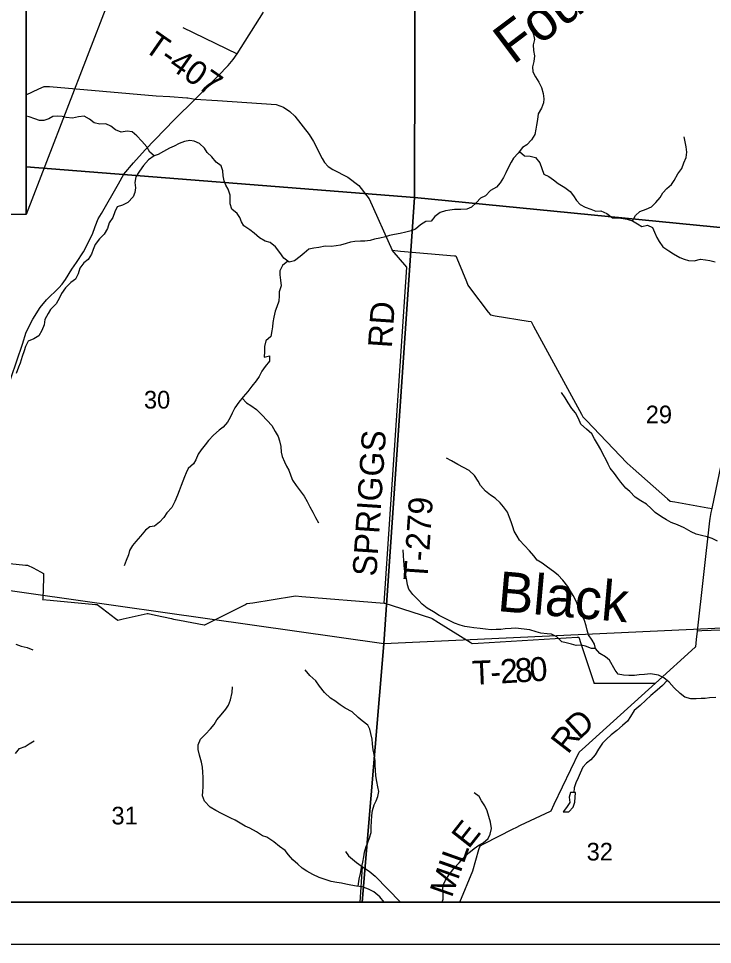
# Model space of a CAD drawing. Extents: x 0 to 34, y 0 to 22.
# Drawn here: x 26.174 to 27.818, y 14 to 16.193 of the extents above; entities that cross this region are included whole.
import ezdxf

# ---------------------------------------------------------------- set-up
doc = ezdxf.new("R2010")
doc.units = 0
for name, color, linetype in [('GM_X_Corporation', 7, 'Continuous'), ('GM_X_County_Road', 7, 'Continuous'), ('GM_X_County_Road_Text', 7, 'Continuous'), ('GM_X_Minor_Lake', 7, 'Continuous'), ('GM_X_Minor_River', 7, 'Continuous'), ('GM_X_Minor_River_Text', 7, 'Continuous'), ('GM_X_Section_Text', 7, 'Continuous'), ('GM_X_State_Route', 7, 'Continuous'), ('GM_X_Township_Road', 7, 'Continuous'), ('GM_X_Township_Road_Text', 7, 'Continuous'), ('SH_Data', 7, 'Continuous')]:
    doc.layers.add(name, color=color, linetype=linetype)

msp = doc.modelspace()

# ---------------------------------------------------------------- linework, layer by layer
at = {"layer": 'GM_X_Corporation'}
for points in [[(25.8273, 14.1), (30.3167, 14.1), (30.3167, 19.5906)], [(26.0314, 16.5691), (26.06, 16.9257), (27.1145, 16.8163), (27.112, 15.7689), (26.1924, 15.8415)], [(26.1924, 15.8415), (27.112, 15.7689), (27.0394, 14.7121), (25.8914, 14.8743), (25.8953, 14.9265), (25.9642, 15.7291)]]:
    msp.add_lwpolyline(points, dxfattribs=at)
for points in [[(27.1145, 16.8163), (28.199, 16.7653), (28.1104, 15.671), (27.112, 15.7689)], [(28.1104, 15.671), (28.0453, 14.7589), (27.0394, 14.7121), (27.112, 15.7689)], [(25.8293, 14.1), (26.9884, 14.1), (27.0394, 14.7121), (25.8914, 14.8743)], [(26.9884, 14.1), (27.9368, 14.1), (28.0453, 14.7589), (27.0394, 14.7121)]]:
    msp.add_lwpolyline(points, close=True, dxfattribs=at)
at = {"layer": 'GM_X_County_Road'}
for points in [[(27.2199, 14.1), (27.2503, 14.1742), (27.2643, 14.2249), (27.2676, 14.2334), (27.2768, 14.2381), (27.3461, 14.2739), (27.353, 14.2774), (27.3636, 14.2824), (27.4341, 14.3158), (27.4357, 14.3165), (27.4434, 14.3325), (27.5026, 14.4554), (27.5169, 14.4686), (27.6831, 14.6189), (27.777, 14.7039), (27.7783, 14.705), (27.7802, 14.7227), (27.7824, 14.7421), (27.8119, 15.0035), (27.8124, 15.0085), (27.8153, 15.0227), (27.8173, 15.0322), (27.9461, 15.6525)], [(28.0576, 14.1), (28.0667, 14.1974), (28.0669, 14.1999), (28.05, 14.2031), (27.953, 14.2215), (27.9558, 14.2408), (28.0358, 14.7517), (27.7925, 14.7425), (27.7824, 14.7421)]]:
    msp.add_lwpolyline(points, dxfattribs=at)
at = {"layer": 'GM_X_Minor_Lake'}
for points in [[(27.4935, 14.3597), (27.4818, 14.3598), (27.4787, 14.3492), (27.4798, 14.3363), (27.4726, 14.3242), (27.4642, 14.3144), (27.4722, 14.3141)], [(27.4722, 14.3141), (27.4775, 14.3139), (27.4877, 14.3253), (27.4923, 14.337), (27.4935, 14.3597)]]:
    msp.add_lwpolyline(points, dxfattribs=at)
at = {"layer": 'GM_X_Minor_River'}
for points in [[(27.3868, 16.1947), (27.3879, 16.1777), (27.389, 16.1678), (27.3939, 16.1553), (27.3961, 16.1431), (27.3934, 16.1306), (27.3937, 16.117), (27.3967, 16.1045), (27.3951, 16.0912), (27.3917, 16.0787), (27.3924, 16.0669), (27.3992, 16.0548), (27.4071, 16.0426), (27.4131, 16.0297), (27.4168, 16.0153), (27.4186, 16.0028), (27.4175, 15.9933), (27.4133, 15.9804), (27.4049, 15.9676), (27.4037, 15.9536), (27.401, 15.9407), (27.3998, 15.9312), (27.3975, 15.9187), (27.3891, 15.9055), (27.3781, 15.8941), (27.3683, 15.8877), (27.358, 15.8741), (27.347, 15.8624), (27.3409, 15.8526), (27.3337, 15.8394), (27.3287, 15.8272), (27.323, 15.8167), (27.3154, 15.8038), (27.3063, 15.7936), (27.2919, 15.7861), (27.2805, 15.7732), (27.2687, 15.7676), (27.2592, 15.7574)], [(26.4951, 15.8676), (26.4853, 15.8763), (26.4778, 15.8889), (26.4661, 15.9026), (26.454, 15.9151), (26.4431, 15.9243), (26.4314, 15.9262), (26.4174, 15.924), (26.4041, 15.9293), (26.3928, 15.9381), (26.3811, 15.9438), (26.3671, 15.9431), (26.3531, 15.9458), (26.3426, 15.9546), (26.3293, 15.9615), (26.3161, 15.9604), (26.3017, 15.9574), (26.2873, 15.9586), (26.2775, 15.9613), (26.2654, 15.9621), (26.2556, 15.961), (26.2461, 15.9557), (26.234, 15.9512), (26.2234, 15.9512), (26.2124, 15.9558), (26.1996, 15.9604), (26.1924, 15.962)], [(27.2592, 15.7574), (27.2471, 15.7461), (27.2361, 15.7412), (27.2221, 15.7408), (27.2073, 15.7409), (27.1956, 15.7394), (27.1854, 15.7372), (27.1729, 15.7335), (27.1604, 15.724), (27.152, 15.7134), (27.1391, 15.7124), (27.1262, 15.7044), (27.1145, 15.6939), (27.1046, 15.6901), (27.0914, 15.6871), (27.0785, 15.6838), (27.0649, 15.6812), (27.0531, 15.6789), (27.0433, 15.676), (27.0304, 15.673), (27.0175, 15.6704), (27.0069, 15.6674), (26.9944, 15.6659), (26.9839, 15.6659), (26.971, 15.6652), (26.9608, 15.6634), (26.9505, 15.6604), (26.9365, 15.6563), (26.9267, 15.6544), (26.9146, 15.6533), (26.9002, 15.6538), (26.8854, 15.6504), (26.8737, 15.6493), (26.8616, 15.6471), (26.8506, 15.6373), (26.8411, 15.629), (26.8282, 15.6195), (26.8149, 15.6162), (26.8029, 15.6257), (26.7935, 15.6386), (26.7825, 15.6523), (26.7705, 15.6626), (26.758, 15.6657), (26.7452, 15.6733), (26.7324, 15.6847), (26.7222, 15.6927), (26.7082, 15.7023), (26.7026, 15.7118), (26.6981, 15.722), (26.692, 15.7315), (26.6792, 15.7414), (26.6751, 15.7543), (26.6755, 15.7642), (26.6752, 15.7748), (26.6707, 15.7888), (26.6651, 15.7987), (26.6609, 15.8089), (26.6591, 15.8207), (26.6584, 15.8321), (26.6539, 15.8442), (26.6426, 15.853), (26.632, 15.8652), (26.6207, 15.8758), (26.6143, 15.8857), (26.6026, 15.8967), (26.5902, 15.9025), (26.5796, 15.904), (26.5675, 15.9018), (26.555, 15.8973), (26.5425, 15.8909), (26.5315, 15.886), (26.5178, 15.8777), (26.5049, 15.871), (26.4951, 15.8676), (26.4822, 15.8585), (26.4704, 15.8446), (26.4609, 15.8313), (26.4521, 15.8181), (26.4498, 15.8044), (26.4513, 15.7919), (26.4494, 15.7806), (26.4459, 15.7707), (26.4334, 15.7571), (26.4201, 15.7507), (26.408, 15.747), (26.4019, 15.7353), (26.3977, 15.7216), (26.3889, 15.7092), (26.3847, 15.6959), (26.3771, 15.6823), (26.3661, 15.6713), (26.3555, 15.6581), (26.3509, 15.6456), (26.3471, 15.635), (26.3391, 15.6222), (26.3292, 15.6142), (26.3193, 15.6014), (26.3155, 15.5881), (26.309, 15.576), (26.2984, 15.5681), (26.2851, 15.5553)], [(27.6286, 15.714), (27.6355, 15.7267), (27.6458, 15.7358), (27.6613, 15.7418), (27.6734, 15.7467), (27.6841, 15.7576), (27.6939, 15.7694), (27.7008, 15.7803), (27.7103, 15.7901), (27.7213, 15.7996), (27.727, 15.8094), (27.7361, 15.8253), (27.7453, 15.8382), (27.7502, 15.8514), (27.7556, 15.8639), (27.7575, 15.8764), (27.7557, 15.8889), (27.7534, 15.9007), (27.7508, 15.9128)], [(27.3608, 15.8779), (27.3724, 15.868), (27.3864, 15.8672), (27.3988, 15.8641), (27.4094, 15.8512), (27.4142, 15.8379), (27.4187, 15.8246), (27.4304, 15.8185), (27.4414, 15.8109), (27.4523, 15.8021), (27.4686, 15.793), (27.481, 15.7831), (27.4885, 15.7732), (27.4961, 15.7622), (27.5043, 15.7527), (27.5168, 15.7462), (27.5296, 15.7412), (27.5421, 15.7366), (27.5538, 15.7373), (27.5682, 15.7312), (27.581, 15.7213), (27.595, 15.7208), (27.6064, 15.7193), (27.6162, 15.7181), (27.629, 15.7139), (27.6407, 15.7066), (27.6506, 15.7002), (27.6642, 15.7035), (27.6759, 15.6978), (27.6811, 15.6868), (27.6864, 15.6746), (27.692, 15.6647), (27.7003, 15.6526), (27.7143, 15.6427), (27.726, 15.6354), (27.7411, 15.627), (27.7509, 15.6228), (27.7611, 15.6201), (27.7751, 15.6193), (27.7895, 15.6227), (27.8012, 15.6215), (27.8122, 15.6196), (27.8246, 15.6169)], [(26.812, 15.6185), (26.7998, 15.6079), (26.7929, 15.5954), (26.7929, 15.5859), (26.7951, 15.573), (26.7962, 15.5601), (26.7912, 15.5461), (26.7916, 15.5363), (26.7908, 15.5238), (26.7858, 15.5102), (26.7824, 15.5003), (26.7793, 15.4859), (26.7762, 15.473), (26.7754, 15.4628), (26.7742, 15.453), (26.7719, 15.4401), (26.7602, 15.4299), (26.7567, 15.4166), (26.7567, 15.4045), (26.7559, 15.3912), (26.7687, 15.3938), (26.7687, 15.3813), (26.7584, 15.3685), (26.7508, 15.3579), (26.744, 15.345), (26.7371, 15.3352), (26.7269, 15.322), (26.7177, 15.3095), (26.7063, 15.2974), (26.6957, 15.2846), (26.6869, 15.271), (26.6801, 15.2585), (26.6755, 15.2479), (26.6694, 15.2373), (26.6592, 15.2252), (26.6493, 15.2177), (26.636, 15.2063), (26.6239, 15.1935), (26.6163, 15.1837), (26.6068, 15.1712), (26.5999, 15.161), (26.5938, 15.1481), (26.5885, 15.1383), (26.5756, 15.127), (26.571, 15.1171), (26.5672, 15.1073), (26.563, 15.0975), (26.5592, 15.0869), (26.5549, 15.0744), (26.5504, 15.0645), (26.5443, 15.049), (26.537, 15.035), (26.5252, 15.0226), (26.518, 15.0116), (26.5078, 15.0003), (26.496, 14.9904), (26.485, 14.9893), (26.4748, 14.9814), (26.4634, 14.9674), (26.452, 14.9546), (26.444, 14.9448), (26.4371, 14.9327), (26.4348, 14.9228), (26.4291, 14.9092), (26.4242, 14.8971)], [(26.2851, 15.5553), (26.2756, 15.542), (26.271, 15.5314), (26.2634, 15.5171), (26.2501, 15.5042), (26.244, 15.4944), (26.2368, 15.4804), (26.2345, 15.4675), (26.2295, 15.4543), (26.2219, 15.4418), (26.2101, 15.4343), (26.1972, 15.4286), (26.1904, 15.4165), (26.1873, 15.4063), (26.1827, 15.3923), (26.1778, 15.3771), (26.1743, 15.3669), (26.1682, 15.3522)], [(26.7037, 15.2942), (26.7138, 15.283), (26.7244, 15.2765), (26.738, 15.267), (26.7501, 15.2544), (26.7632, 15.2411), (26.7738, 15.2289), (26.7821, 15.2153), (26.7892, 15.2031), (26.7926, 15.1932), (26.7952, 15.1796), (26.7966, 15.1659), (26.7985, 15.1557), (26.8045, 15.1432), (26.8086, 15.1329), (26.8143, 15.1234), (26.8195, 15.1101), (26.8233, 15.0999), (26.8319, 15.0873), (26.8511, 15.0615), (26.8579, 15.049), (26.8639, 15.0364), (26.871, 15.0235), (26.8778, 15.011), (26.8845, 14.9988)], [(27.8298, 14.9554), (27.8177, 14.9615), (27.8056, 14.9657), (27.792, 14.9688), (27.7791, 14.9719), (27.7678, 14.9772), (27.7512, 14.9868), (27.7353, 14.9937), (27.7202, 14.9994), (27.7089, 15.0055), (27.6972, 15.0131), (27.6825, 15.0234), (27.6727, 15.0326), (27.6614, 15.0425), (27.6485, 15.0505), (27.6349, 15.0596), (27.6225, 15.0725), (27.6127, 15.0809), (27.601, 15.0946), (27.5939, 15.1041), (27.586, 15.1155), (27.5754, 15.1281), (27.5709, 15.1379), (27.566, 15.1478), (27.5589, 15.1607), (27.5536, 15.1725), (27.5454, 15.1854), (27.5386, 15.1972), (27.5322, 15.2094), (27.5198, 15.2204), (27.5062, 15.2322), (27.501, 15.2455), (27.4938, 15.2588), (27.4852, 15.2694), (27.4761, 15.2831), (27.4694, 15.2949), (27.4607, 15.307)], [(27.7796, 14.5819), (27.7671, 14.5815), (27.7524, 14.5854), (27.7418, 14.5941), (27.7271, 14.6078), (27.7154, 14.6211), (27.703, 14.6314), (27.6901, 14.6379), (27.6712, 14.6406), (27.6572, 14.6396), (27.6447, 14.6385), (27.633, 14.637), (27.6201, 14.6374), (27.6073, 14.6375), (27.5944, 14.6402), (27.5873, 14.6497), (27.5741, 14.6736), (27.5643, 14.6812), (27.5511, 14.6889), (27.5413, 14.701), (27.5387, 14.7113), (27.5334, 14.7211), (27.524, 14.7333), (27.5214, 14.7447), (27.5192, 14.7549), (27.5147, 14.7671), (27.5087, 14.7804), (27.5034, 14.7902), (27.4993, 14.8032), (27.4948, 14.8134), (27.4884, 14.8267), (27.4817, 14.8366), (27.4756, 14.848), (27.4636, 14.8632), (27.4527, 14.875), (27.4414, 14.883), (27.427, 14.8936), (27.4149, 14.9032), (27.4029, 14.9104), (27.3946, 14.9207), (27.3844, 14.9325), (27.3611, 14.9576), (27.3554, 14.9671), (27.3486, 14.9792), (27.3453, 14.9891), (27.3412, 15.0009), (27.3374, 15.0115), (27.3325, 15.0236), (27.3228, 15.0362), (27.3148, 15.0457), (27.3035, 15.0567), (27.2922, 15.064), (27.2801, 15.0739), (27.2685, 15.0868), (27.2632, 15.0971), (27.2546, 15.1111), (27.2417, 15.1225), (27.2285, 15.1298), (27.2146, 15.1367), (27.2002, 15.1454), (27.1877, 15.1515)], [(27.5417, 14.7006), (27.5315, 14.7011), (27.5171, 14.7068), (27.5073, 14.7087), (27.4948, 14.708), (27.4838, 14.7111), (27.4718, 14.7146), (27.4615, 14.7169), (27.4495, 14.7283), (27.437, 14.7348), (27.4264, 14.7356), (27.4117, 14.7375), (27.4007, 14.7402), (27.3856, 14.7452), (27.3652, 14.7479), (27.3523, 14.7488), (27.341, 14.7484), (27.3266, 14.7473), (27.3168, 14.7462), (27.3054, 14.7459), (27.2941, 14.7452), (27.2804, 14.7464), (27.2676, 14.7487), (27.2528, 14.7499), (27.2423, 14.7518), (27.2317, 14.7534), (27.2207, 14.7565), (27.2067, 14.7611), (27.1803, 14.7744), (27.1705, 14.779), (27.1573, 14.7882), (27.1418, 14.7966), (27.1305, 14.8057), (27.1218, 14.8156), (27.1082, 14.8285), (27.0985, 14.8418), (27.0955, 14.8521), (27.094, 14.8619), (27.0918, 14.8748), (27.0888, 14.8885), (27.0877, 14.8991), (27.0866, 14.9086), (27.0863, 14.9211), (27.0852, 14.9344)], [(26.1677, 14.7112), (26.1806, 14.7066), (26.1949, 14.7035), (26.2082, 14.6978)], [(26.9785, 14.1379), (26.9813, 14.1548), (26.9844, 14.1684), (26.9867, 14.1817), (26.9894, 14.1953), (26.9921, 14.2078), (26.9936, 14.2184), (26.9978, 14.232), (27.0013, 14.2419), (27.0059, 14.2525), (27.0093, 14.2653), (27.0097, 14.2786), (27.0102, 14.2915), (27.011, 14.3051), (27.0125, 14.3172), (27.0164, 14.3305), (27.0213, 14.3403), (27.0251, 14.3502), (27.0278, 14.3623), (27.0252, 14.3733), (27.0226, 14.3862), (27.0208, 14.3991), (27.0201, 14.4139), (27.019, 14.4248), (27.019, 14.4347), (27.0164, 14.4499), (27.0142, 14.4609), (27.0127, 14.4749), (27.0116, 14.4859), (27.009, 14.4995), (27.0061, 14.5098), (27.0016, 14.5197), (26.9884, 14.5299), (26.9785, 14.5379), (26.9642, 14.5509), (26.948, 14.5597), (26.9363, 14.5677), (26.9231, 14.5768), (26.9129, 14.5837), (26.8986, 14.597), (26.8873, 14.6118), (26.8786, 14.6247), (26.8643, 14.6369), (26.8534, 14.6502)], [(26.6117, 14.373), (26.6114, 14.3828), (26.6118, 14.3957), (26.6107, 14.4082), (26.61, 14.4203), (26.6078, 14.4321), (26.6029, 14.448), (26.5996, 14.4617), (26.5996, 14.4727), (26.6053, 14.4863), (26.6167, 14.4984), (26.6289, 14.5109), (26.6373, 14.5211), (26.6441, 14.532), (26.654, 14.5441), (26.665, 14.557), (26.6718, 14.5668), (26.6764, 14.5793), (26.6799, 14.5967), (26.6811, 14.61)], [(27.7108, 14.625), (27.6999, 14.6136), (27.6873, 14.6027), (27.6722, 14.5899), (27.6604, 14.5785), (27.6464, 14.5657), (27.6327, 14.554), (27.6239, 14.54), (27.6171, 14.5291), (27.6046, 14.5185), (27.5913, 14.5068), (27.5784, 14.4962), (27.5674, 14.486), (27.5575, 14.4766), (27.5484, 14.4622), (27.5404, 14.4494), (27.5297, 14.4373), (27.5199, 14.4297), (27.5111, 14.4199), (27.5047, 14.4059), (27.4997, 14.395), (27.494, 14.3829), (27.4901, 14.3711), (27.4896, 14.3598)], [(27.8257, 14.5847), (27.811, 14.5844), (27.8008, 14.5829), (27.7909, 14.5826), (27.7796, 14.5819)], [(26.1672, 14.4524), (26.1767, 14.4644), (26.1895, 14.4686), (26.199, 14.4754), (26.2111, 14.4825)], [(27.0402, 14.1), (27.0299, 14.1125), (27.0156, 14.1243), (27.0031, 14.1308), (26.9884, 14.1366), (26.9744, 14.1385), (26.9612, 14.1405), (26.9495, 14.1428), (26.9393, 14.1451), (26.9283, 14.1466), (26.9147, 14.149), (26.9007, 14.1536), (26.886, 14.1589), (26.8716, 14.1654), (26.8569, 14.1738), (26.846, 14.1807), (26.8354, 14.1906), (26.8241, 14.2001), (26.8135, 14.2123), (26.8056, 14.2225), (26.7924, 14.2321), (26.7792, 14.2431), (26.7626, 14.2538), (26.7524, 14.2576), (26.7377, 14.2671), (26.7222, 14.2751), (26.7109, 14.2805), (26.6988, 14.2874), (26.6871, 14.2942), (26.6769, 14.2988), (26.6648, 14.3053), (26.6546, 14.3103), (26.6418, 14.3171), (26.6282, 14.3255), (26.615, 14.3392), (26.6101, 14.3521), (26.6109, 14.3624), (26.6117, 14.373)], [(27.1776, 14.1), (27.1797, 14.1074), (27.1801, 14.118), (27.179, 14.1301), (27.1802, 14.1408), (27.1859, 14.1525), (27.1954, 14.1665), (27.205, 14.1801), (27.2182, 14.1937), (27.2266, 14.2035), (27.2407, 14.2167), (27.2539, 14.2276), (27.2649, 14.2352), (27.2748, 14.2408), (27.2869, 14.251), (27.2915, 14.2612), (27.2942, 14.2749), (27.292, 14.2893), (27.2879, 14.3033), (27.2841, 14.3162), (27.2789, 14.328), (27.271, 14.3405), (27.2654, 14.3504), (27.2537, 14.3595)]]:
    msp.add_lwpolyline(points, dxfattribs=at)
at = {"layer": 'GM_X_State_Route'}
msp.add_lwpolyline([(26.1429, 15.303), (26.1832, 15.4214), (26.1922, 15.4498), (26.2078, 15.481), (26.2255, 15.5086), (26.2404, 15.5264), (26.2693, 15.5555), (26.2776, 15.5641), (26.2852, 15.5752), (26.3003, 15.5991), (26.3118, 15.6155), (26.3281, 15.6403), (26.3493, 15.6819), (26.3557, 15.7007), (26.3626, 15.7189), (26.3703, 15.7311), (26.4113, 15.8016), (26.4236, 15.8242), (26.4462, 15.8509), (26.4738, 15.8821), (26.5433, 15.954), (26.5927, 16.0024), (26.6473, 16.0575), (26.6709, 16.0819), (26.6827, 16.0959), (26.692, 16.109), (26.7547, 16.208)], dxfattribs=at)
at = {"layer": 'GM_X_Township_Road'}
for p, q in [((26.5632, 16.1719), (26.692, 16.109)), ((26.9835, 14.1), (26.9893, 14.1836))]:
    msp.add_line(p, q, dxfattribs=at)
for points in [[(26.1924, 16.0122), (26.2225, 16.0268), (26.2346, 16.0318), (26.2475, 16.0318), (26.5, 16.0096), (26.5325, 16.0086), (26.5732, 16.0053)], [(26.5732, 16.0053), (26.5752, 16.0051), (26.5927, 16.0024), (26.6452, 15.9992), (26.7843, 15.9896), (26.8021, 15.9829), (26.8171, 15.9731), (26.8285, 15.9615), (26.863, 15.9186), (26.8728, 15.9021), (26.8936, 15.8614), (26.899, 15.8517), (26.9079, 15.8429), (26.919, 15.8357), (26.9545, 15.817), (26.9801, 15.7975), (27.0048, 15.7657), (27.0593, 15.6441), (27.0789, 15.6423), (27.2069, 15.6313), (27.21, 15.631), (27.2164, 15.6156), (27.2353, 15.5699), (27.2388, 15.5615), (27.2452, 15.553), (27.2868, 15.4977), (27.2919, 15.4909), (27.303, 15.4891), (27.3811, 15.4765), (27.3887, 15.4753), (27.3944, 15.4647), (27.5075, 15.2561), (27.5112, 15.2493), (27.5195, 15.2406), (27.6152, 15.1406), (27.6159, 15.1399), (27.63, 15.1275), (27.7115, 15.0556), (27.7176, 15.0503), (27.7291, 15.0482), (27.8069, 15.0341), (27.8173, 15.0322)], [(27.0402, 14.8081), (27.0937, 15.6038), (27.0593, 15.6441)], [(26.1229, 14.9053), (26.1905, 14.8985), (26.1952, 14.8984), (26.2085, 14.8917), (26.226, 14.8828), (26.2335, 14.879), (26.2331, 14.8679), (26.2313, 14.8189), (26.2312, 14.8171), (26.2489, 14.8154), (26.3562, 14.8054), (26.3606, 14.8049), (26.3727, 14.7958), (26.404, 14.7723), (26.4095, 14.7681), (26.4219, 14.7709), (26.4792, 14.7837), (26.4809, 14.7841), (26.4983, 14.7802), (26.5366, 14.7718), (26.5412, 14.7708), (26.5558, 14.7681), (26.6136, 14.7574), (26.6151, 14.7571), (26.6313, 14.7652), (26.7101, 14.8046), (26.7153, 14.8072), (26.7289, 14.8094), (26.8256, 14.8251), (26.8299, 14.8258), (26.845, 14.8245), (27.0402, 14.8081), (27.0419, 14.808), (27.0589, 14.8025), (27.1522, 14.7725), (27.1542, 14.7719), (27.169, 14.7627), (27.2439, 14.7162), (27.2491, 14.713), (27.2626, 14.7138), (27.4972, 14.7276), (27.5013, 14.7278), (27.5061, 14.7131), (27.5367, 14.6201), (27.537, 14.6192), (27.5556, 14.6192), (27.6731, 14.6189), (27.6831, 14.6189)], [(26.9486, 14.2201), (26.956, 14.2102), (26.9744, 14.1939), (26.9893, 14.1836), (27.0045, 14.1737), (27.0189, 14.1616), (27.0791, 14.1)]]:
    msp.add_lwpolyline(points, dxfattribs=at)
at = {"layer": 'SH_Data'}
for points in [[(23.4167, 21), (30.4167, 21), (30.4167, 14), (23.4167, 14)], [(23.5167, 20.9), (30.3167, 20.9), (30.3167, 14.1), (23.5167, 14.1)], [(26.1924, 16.5691), (26.7223, 17.1016), (26.1924, 15.7291)], [(24.3169, 16.5691), (26.1924, 16.5691), (26.1924, 15.7291), (24.3169, 15.7291)]]:
    msp.add_lwpolyline(points, close=True, dxfattribs=at)

# ---------------------------------------------------------------- texts
at = {"layer": 'GM_X_County_Road_Text'}
for s, rotation, p in [('D', 42.6295, (27.5025, 14.4837)), ('R', 52.3307, (27.4757, 14.4487)), ('E', 51.804, (27.2404, 14.2248)), ('L', 70.4768, (27.2286, 14.1891)), ('I', 70.6431, (27.2208, 14.1671)), ('M', 70.6422, (27.2004, 14.1089))]:
    msp.add_text(s, height=0.0568, rotation=rotation, dxfattribs=at).set_placement(p)
at = {"layer": 'GM_X_Minor_River_Text'}
for s, rotation, p in [('Fourmile', 37.0021, (27.3461, 16.0821)), ('Black', 354.9973, (27.3066, 14.7899))]:
    msp.add_text(s, height=0.0947, rotation=rotation, dxfattribs=at).set_placement(p)
at = {"layer": 'GM_X_Section_Text'}
for s, p in [('30', (26.4712, 15.2693)), ('29', (27.66, 15.2343)), ('31', (26.3942, 14.2843)), ('32', (27.52, 14.1989))]:
    msp.add_text(s, height=0.04186, rotation=0, dxfattribs=at).set_placement(p)
at = {"layer": 'GM_X_Township_Road_Text'}
for s, height, rotation, p in [('T-407', 0.05682, 325.0239, (26.4679, 16.119)), ('RD', 0.05682, 86.0533, (27.0585, 15.4116)), ('SPRIGGS', 0.05682, 86.164, (27.0218, 14.8707)), ('T-279', 0.05682, 86.0741, (27.1425, 14.86)), ('T', 0.0568, 2.4778, (27.2498, 14.6148)), ('2', 0.0568, 3.5666, (27.3167, 14.6181)), ('8', 0.0568, 3.6152, (27.3517, 14.6203)), ('0', 0.0568, 3.6307, (27.3867, 14.6225)), ('-', 0.0568, 3.3939, (27.2933, 14.6167))]:
    msp.add_text(s, height=height, rotation=rotation, dxfattribs=at).set_placement(p)

doc.saveas('drawing.dxf')
